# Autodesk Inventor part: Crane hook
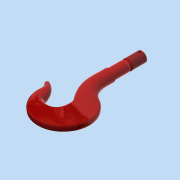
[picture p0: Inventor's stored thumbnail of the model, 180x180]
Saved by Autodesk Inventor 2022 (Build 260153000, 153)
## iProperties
Created: 2022-03
Part Number: Crane hook
Material: Acciaio, Alta resistenza, Bassa lega
Document SubType Name: Modeling
Designer: HONG VAN
Density: 7.85 g/cm^3
Appearance: Liscia - Rosso
Mass: 4194.92 g
Surface Area: 596.4 cm^2
Volume: 534.384 cm^3
Author: HONG VAN
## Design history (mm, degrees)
workplane "Work Plane2"
sketch "Sketch5"
  geometry: L1 (-34.174, 20)-(-34.174, -20); L2 (-38.639, -18.646)-(-72.315, -8.433); L3 (-75.391, -7.5)-(-75.391, 7.5); L4 (-72.315, 8.433)-(-38.639, 18.646); L5 (-34.174, 0)-(-75.391, 0); L6 (-30, 0)-(-76.035, 0) reference; A1 r 44 centre (-32.035, 0) between (-75.842, 4.116) and (-75.842, -4.116); A2 r 50 centre (-80, 0) between (-32.431, -15.401) and (-32.431, 15.401); A3 r 5 centre (-37.188, -13.861) between (-38.639, -18.646) and (-32.431, -15.401); A4 r 5 centre (-37.188, 13.861) between (-32.431, 15.401) and (-38.639, 18.646); A5 r 5 centre (-70.864, 3.648) between (-72.315, 8.433) and (-75.842, 4.116); A6 r 5 centre (-70.864, -3.648) between (-75.842, -4.116) and (-72.315, -8.433); 2 further points
  constraints: 18 point on circle, 10 end point, 8 tangent, 6 centre point, 4 point on line, 2 equal radius, 2 midpoint, 1 horizontal, 1 parallel, 1 vertical
  dimensions: "d51" = 40 distance of L1.start L1.end; "d52" = 15 distance of L3.start L3.end; "d53" = 44 radius of A1; "d54" = 50 radius of A2; "d55" = 5 radius of A3; "d56" = 5 radius of A5
sketch "Sketch7"
  geometry: C1 r 17.5 at (-17.5, 0); 1 further point
  constraints: 1 centre point, 1 coincident
  dimensions: "d59" = 35 diameter of C1
sketch "Sketch8"
  geometry: L1 (62.5, 0)-(31.013, 0) reference; A1 r 15.743 centre (46.757, 0) between (62.5, 0) and (31.013, 0); 1 further point
  constraints: 2 point on circle, 1 centre point, 1 midpoint
  dimensions: "d71" = 31.48662 diameter of A1 (derived)
workplane "Work Plane5"
workplane "Work Plane6"
sketch "Sketch14"
  geometry: C1 r 17.5 at (17.5, 0); 1 further point
  constraints: 1 centre point, 1 coincident
  dimensions: "d108" = 35 diameter of C1
sketch "Sketch4"
  geometry: L1 (-37.596, -22.087)-(-88.678, -8.398); L2 (-88.678, 8.398)-(-37.596, 22.087); L3 (-32.324, -23.5)-(-32.324, 23.5); L4 (-30, 0)-(-92.5, 0) reference; A1 r 120 centre (-150, 0) between (-31.359, -18.008) and (-31.359, 18.008); A2 r 60 centre (-32.5, 0) between (-92.374, 3.893) and (-92.374, -3.893); A3 r 5 centre (-36.302, -17.257) between (-37.596, -22.087) and (-31.359, -18.008); A4 r 5 centre (-36.302, 17.257) between (-31.359, 18.008) and (-37.596, 22.087); A5 r 5 centre (-87.384, 3.568) between (-88.678, 8.398) and (-92.374, 3.893); A6 r 5 centre (-87.384, -3.568) between (-92.374, -3.893) and (-88.678, -8.398); 5 further points; 1 other entity
  constraints: 22 point on circle, 8 point on line, 8 tangent, 6 centre point, 6 end point, 3 equal radius, 1 vertical, 1 vertical alignment, 3 other
  dimensions: "d42" = 15 distance of point (-92.029, 7.5) point (-92.029, -7.5); "d43" = 47 distance of L3.start L3.end; "d45" = 120 radius of A1; "d48" = 60 radius of A2; "d156" = 5 radius of A3
sketch "Sketch15"
  geometry: A1 r 5.887 centre (5.887, 0) between (0, 0) and (11.774, 0); 1 further point
  constraints: 2 point on circle, 1 centre point, 1 horizontal alignment
sketch "Sketch2"
  geometry: L1 (17.5, 128.452)-(17.5, 150); L2 (17.5, 150)-(-17.5, 150); L3 (-17.5, 150)-(-17.5, 123.769); L4 (30, 0)-(92.5, 0); L5 (0, -30)-(0, -76.035); L6 (-62.5, 0)-(-31.013, 0); L7 (-66.307, 41.362)-(-73.526, 32.061); A1 r 30 centre (0, 0) between (-29.319, -6.357) and (22.297, 20.071); A2 r 77.5 centre (15, 0) between (-62.484, 1.596) and (53.093, 67.492); A3 r 70 centre (87.5, 128.452) between (17.5, 128.452) and (53.093, 67.492); A4 r 155 centre (137.5, 123.769) between (-17.5, 123.769) and (22.297, 20.071); A5 r 45 centre (-107.474, 2.522) between (-62.484, 1.596) and (-73.526, 32.061); A6 r 70 centre (-97.729, -21.189) between (-29.319, -6.357) and (-66.307, 41.362); A7 r 6 centre (-69, 36) between (-66.307, 41.362) and (-73.526, 32.061); 2 further points
  constraints: 20 point on circle, 14 end point, 8 tangent, 7 centre point, 3 point on line, 2 horizontal, 2 perpendicular, 2 vertical, 1 coincident, 1 horizontal alignment, 1 midpoint, 1 vertical alignment
  dimensions: "d0" = 30 radius of A1; "d1" = 155 diameter of A2; "d13" = 70 radius of A3; "d17" = 155 radius of A4; "d18" = 35 distance between parallel lines of L3 L1; "d20" = 15 distance of A2.centre point (0, 0); "d21" = 150 distance from line of L2 point (0, 0); "d27" = 45 radius of A5; "d29" = 70 radius of A6; "d31" = 6 radius of A7; "d32" = 69 horizontal distance of A7.centre point (0, 0); "d34" = 36 vertical distance of A7.centre point (0, 0)
loft "Loft7" sketch "Sketch14", "Sketch4", "Sketch15", "Sketch2" dims "d158" = 0, "d159" = 90 deg, "d160" = 0, "d161" = 90 deg, "d162" = 0, "d163" = 90 deg, "d164" = 0, "d165" = 90 deg, "d166" = 0, "d167" = 90 deg, "d168" = 0, "d169" = 90 deg, "d170" = 0, "d171" = 90 deg, "d196" = 0, "d197" = 90 deg
sketch "Sketch16"
  geometry: L1 (-66.307, 41.362)-(-69.916, 36.711); L2 (-73.739, 39.679)-(-69.916, 36.711); L3 (-127.63, -37.632)-(-23.508, 96.492) reference; A1 r 6 centre (-69, 36) between (-66.307, 41.362) and (-73.526, 32.061); A2 r 70 centre (-97.729, -21.189) between (-29.319, -6.357) and (-66.307, 41.362) reference; A3 r 6 centre (-69, 36) between (-66.307, 41.362) and (-73.526, 32.061) reference; 1 further point
  constraints: 4 point on line, 3 end point, 2 point on circle, 2 tangent, 1 centre point, 1 collinear, 1 perpendicular
revolve "Revolution1" sketch "Sketch16" stored, may be unused: angle "d175" = 90 deg
sketch "Sketch17"
  geometry: L1 (-17.5, 150)-(17.5, 150) reference; L2 (0, 150)-(0, 245); L3 (0, 245)-(15, 245); L4 (15, 245)-(15, 200); L5 (15, 200)-(12.5, 200); L6 (12.5, 200)-(12.5, 195); L7 (12.5, 195)-(15, 195); L8 (15, 195)-(15, 150); 1 further point
  constraints: 14 end point, 2 horizontal, 2 parallel, 2 perpendicular, 1 midpoint, 1 point on line, 1 vertical
  dimensions: "d176" = 30 diameter of L8 L2; "d177" = 30 diameter of L4 L2; "d178" = 25 diameter of L6 L2; "d179" = 45 distance from line of L6.end L1; "d181" = 5 distance of L5.end L6.end; "d183" = 95 distance between parallel lines of L1 L3; "d195" = 45 distance from line of L3 L5.end (derived)
revolve "Revolution2" sketch "Sketch17" stored, may be unused: angle "d184" = 90 deg
sketch "Sketch18"
  geometry: L1 (-15, 245)-(15, 245) reference; L2 (-15, 200)-(15, 200) reference; C1 r 3.1 at (0, 237); 2 further points
  constraints: 1 centre point, 1 midpoint, 1 vertical alignment
  dimensions: "d185" = 6.2 diameter of C1; "d186" = 8 distance from line of C1.centre L1
extrude "Extrusion1" cut sketch "Sketch18" extent not by distance; stored distance "d187" = 10; taper "d188" = 0 deg
chamfer "Chamfer1" distance "d189" = 1; stored, may be unused: second distance "d190" = 2, angle "d191" = 45 deg
fillet "Fillet1" dims "d192" = 1
thread "Thread1" dims "d193" = 10, "d194" = 0
chamfer "Chamfer2" distance "d198" = 2.5; stored, may be unused: second distance "d199" = 2, angle "d200" = 45 deg
sketch "Schizzo20"
  geometry: L1 (2.5, -29.136)-(-2.5, -29.136); L2 (-2.5, -29.136)-(-2.5, -30.136); L3 (-2.5, -30.136)-(2.5, -30.136); L4 (2.5, -30.136)-(2.5, -29.136); L5 (0, -30.136)-(0, -26.745); 1 further point
  constraints: 10 end point, 2 parallel, 1 horizontal, 1 midpoint, 1 perpendicular, 1 vertical, 1 other
  dimensions: "d204" = 5 distance of L3.end L2.end; "d205" = 1 distance of L2.end L1.end
extrude "Estrusione3" cut sketch "Schizzo20" stored distance "d206" = 100; taper "d207" = 0 deg
sketch "Schizzo21"
  geometry: L1 (5, 9.699)-(5, 0.191) reference; L2 (0, 9.889)-(0, 0) reference; 1 further point
  constraints: 2 other
  node "Linea chiusa proiettata5"
body "Solid5"
node "Projected Loop4"
other parameters: "d172" = 90 deg, "sa_0" = 9810000
